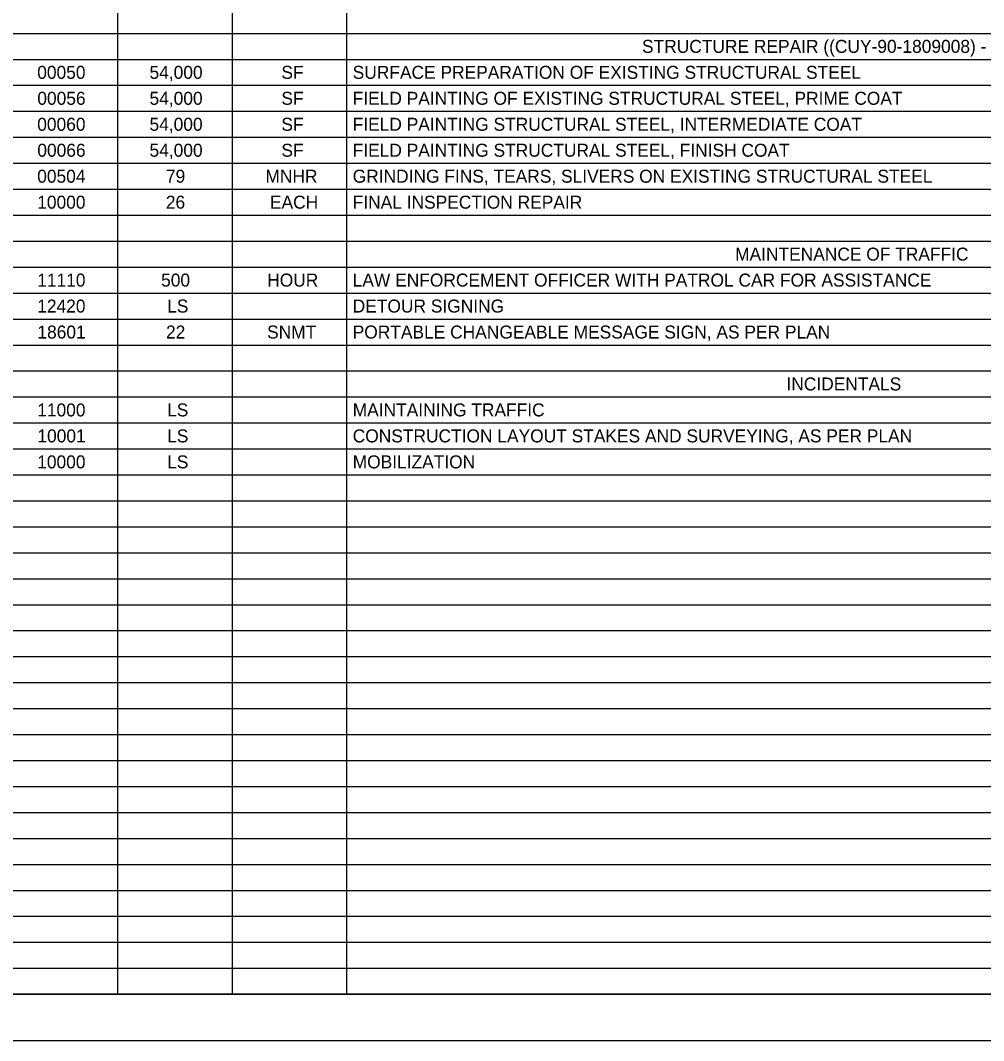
# Model space of a CAD drawing. Extents: x 0 to 34, y 0 to 22.
# Drawn here: x 16.99 to 27.38, y 0 to 11 of the extents above; entities that cross this region are included whole.
import ezdxf

# ---------------------------------------------------------------- set-up
doc = ezdxf.new("R2010")
doc.units = 0
for name, color, linetype in [('SH_Border', 7, 'Continuous'), ('SH_Cut_Line', 7, 'Continuous'), ('SH_Data', 7, 'Continuous'), ('SH_Text', 7, 'Continuous')]:
    doc.layers.add(name, color=color, linetype=linetype)

msp = doc.modelspace()

# ---------------------------------------------------------------- linework, layer by layer
at = {"layer": 'SH_Border'}
msp.add_lwpolyline([(1.5, 21.5), (33.5, 21.5), (33.5, 0.5), (1.5, 0.5)], close=True, dxfattribs=at)
at = {"layer": 'SH_Cut_Line'}
msp.add_lwpolyline([(0, 0), (34, 0), (34, 22), (0, 22)], close=True, dxfattribs=at)
at = {"layer": 'SH_Data'}
for p, q in [((18.036, 21.5), (18.036, 0.5)), ((19.272, 21.5), (19.272, 0.5)), ((20.507, 21.5), (20.507, 0.5)), ((1.5, 10.86), (32.004, 10.86)), ((1.5, 10.58), (32.004, 10.58)), ((1.5, 10.3), (32.004, 10.3)), ((1.5, 10.02), (32.004, 10.02)), ((1.5, 9.74), (32.004, 9.74)), ((1.5, 9.46), (32.004, 9.46)), ((1.5, 9.18), (32.004, 9.18)), ((1.5, 8.9), (32.004, 8.9)), ((1.5, 8.62), (32.004, 8.62)), ((1.5, 8.34), (32.004, 8.34)), ((1.5, 8.06), (32.004, 8.06)), ((1.5, 7.78), (32.004, 7.78)), ((1.5, 7.5), (32.004, 7.5)), ((1.5, 7.22), (32.004, 7.22)), ((1.5, 6.94), (32.004, 6.94)), ((1.5, 6.66), (32.004, 6.66)), ((1.5, 6.38), (32.004, 6.38)), ((1.5, 6.1), (32.004, 6.1)), ((1.5, 5.82), (32.004, 5.82)), ((1.5, 5.54), (32.004, 5.54)), ((1.5, 5.26), (32.004, 5.26)), ((1.5, 4.98), (32.004, 4.98)), ((1.5, 4.7), (32.004, 4.7)), ((1.5, 4.42), (32.004, 4.42)), ((1.5, 4.14), (32.004, 4.14)), ((1.5, 3.86), (32.004, 3.86)), ((1.5, 3.58), (32.004, 3.58)), ((1.5, 3.3), (32.004, 3.3)), ((1.5, 3.02), (32.004, 3.02)), ((1.5, 2.74), (32.004, 2.74)), ((1.5, 2.46), (32.004, 2.46)), ((1.5, 2.18), (32.004, 2.18)), ((1.5, 1.9), (32.004, 1.9)), ((1.5, 1.62), (32.004, 1.62)), ((1.5, 1.34), (32.004, 1.34)), ((1.5, 1.06), (32.004, 1.06)), ((1.5, 0.78), (32.004, 0.78)), ((1.5, 0.5), (32.004, 0.5))]:
    msp.add_line(p, q, dxfattribs=at)

# ---------------------------------------------------------------- texts
at = {"layer": 'SH_Text'}
for s, p in [('STRUCTURE REPAIR ((CUY-90-1809008) - LOCATION 4)', (23.693, 10.65)), ('00050', (17.171, 10.37)), ('54,000', (18.382, 10.37)), ('SF', (19.804, 10.37)), ('SURFACE PREPARATION OF EXISTING STRUCTURAL STEEL', (20.573, 10.37)), ('00056', (17.172, 10.09)), ('54,000', (18.382, 10.09)), ('SF', (19.804, 10.09)), ('FIELD PAINTING OF EXISTING STRUCTURAL STEEL, PRIME COAT', (20.573, 10.09)), ('00060', (17.171, 9.81)), ('54,000', (18.382, 9.81)), ('SF', (19.804, 9.81)), ('FIELD PAINTING STRUCTURAL STEEL, INTERMEDIATE COAT', (20.573, 9.81)), ('00066', (17.172, 9.53)), ('54,000', (18.382, 9.53)), ('SF', (19.804, 9.53)), ('FIELD PAINTING STRUCTURAL STEEL, FINISH COAT', (20.573, 9.53)), ('00504', (17.171, 9.25)), ('79', (18.559, 9.25)), ('MNHR', (19.632, 9.25)), ('GRINDING FINS, TEARS, SLIVERS ON EXISTING STRUCTURAL STEEL', (20.573, 9.25)), ('10000', (17.171, 8.97)), ('26', (18.558, 8.97)), ('EACH', (19.681, 8.97)), ('FINAL INSPECTION REPAIR', (20.573, 8.97)), ('MAINTENANCE OF TRAFFIC', (24.697, 8.41)), ('11110', (17.171, 8.13)), ('500', (18.507, 8.13)), ('HOUR', (19.651, 8.13)), ('LAW ENFORCEMENT OFFICER WITH PATROL CAR FOR ASSISTANCE', (20.573, 8.13)), ('12420', (17.171, 7.85)), ('LS', (18.572, 7.85)), ('DETOUR SIGNING', (20.573, 7.85)), ('18601', (17.173, 7.57)), ('22', (18.56, 7.57)), ('SNMT', (19.65, 7.57)), ('PORTABLE CHANGEABLE MESSAGE SIGN, AS PER PLAN', (20.573, 7.57)), ('INCIDENTALS', (25.251, 7.01)), ('11000', (17.171, 6.73)), ('LS', (18.572, 6.73)), ('MAINTAINING TRAFFIC', (20.573, 6.73)), ('10001', (17.173, 6.45)), ('LS', (18.572, 6.45)), ('CONSTRUCTION LAYOUT STAKES AND SURVEYING, AS PER PLAN', (20.573, 6.45)), ('10000', (17.171, 6.17)), ('LS', (18.572, 6.17)), ('MOBILIZATION', (20.573, 6.17))]:
    msp.add_text(s, height=0.14, dxfattribs=at).set_placement(p)

doc.saveas('drawing.dxf')
